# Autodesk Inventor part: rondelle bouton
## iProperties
Created: 2001-11
Part Number: rondelle bouton
Material: Par défaut
Document SubType Name: Modélisation
Designer: User
Control State: 0
Master: False
Checked Out: False
Shininess: 20.0
Length Units: 11269
Angle Units: 11279
Time Units: 11290
Mass Units: 11283
Length Display Precision: 3
Angle Display Precision: 2
Density: 0.0
Volumn: 0.0
Area: 0.0
PropertySet Name: Model Information
Author: User
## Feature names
1. Extrusion1
